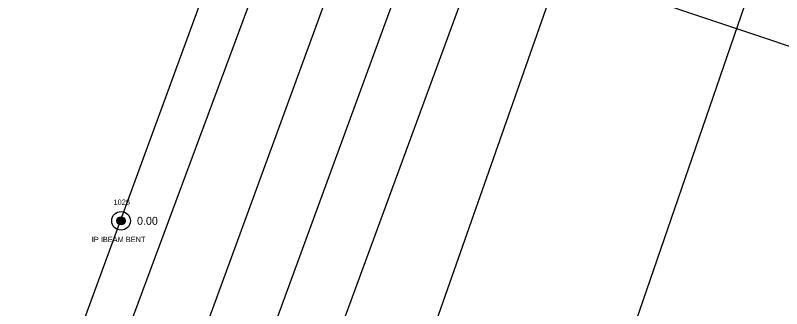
# Model space of a CAD drawing. Extents: x 2139392 to 2143384, y 505395 to 510520.
# Drawn here: x 2140882.2 to 2141025.8, y 508983.1 to 509038.2 of the extents above; entities that cross this region are included whole.
import ezdxf

# ---------------------------------------------------------------- set-up
doc = ezdxf.new("R2010")
doc.units = 0
for name, color, linetype in [('RD_EV_EX_Wetlands', 7, 'Continuous'), ('RD_EX_DV_Prop_txCode', 7, 'Continuous'), ('RD_EX_DV_PropPin', 7, 'Continuous'), ('RD_EX_H2O', 7, 'Continuous'), ('RD_EX_Road', 7, 'Continuous'), ('RD_EX_TX_DV_Prop_ELEV', 7, 'Continuous'), ('RD_EX_VEG', 7, 'Continuous'), ('RD_HC_Cl', 7, 'Continuous'), ('RD_HC_Data', 7, 'Continuous'), ('RD_SMD_Locator', 7, 'Continuous')]:
    doc.layers.add(name, color=color, linetype=linetype)

msp = doc.modelspace()

# ---------------------------------------------------------------- linework, layer by layer
at = {"layer": 'RD_EV_EX_Wetlands'}
for p, q in [((2141031.31, 509324.16), (2140691.53, 508408.63)), ((2141075.3, 509306.14), (2140751.4, 508384.33))]:
    msp.add_line(p, q, dxfattribs=at)
at = {"layer": 'RD_EX_DV_PropPin'}
for p, q in [((2140901.28, 508999.35), (2140901.28, 508999.94)), ((2140901.32, 508999.27), (2140901.32, 509000.01)), ((2140901.35, 508999.22), (2140901.35, 509000.07)), ((2140901.39, 508999.17), (2140901.39, 509000.12)), ((2140901.42, 508999.13), (2140901.42, 509000.16)), ((2140901.46, 508999.09), (2140901.46, 509000.19)), ((2140901.49, 508999.06), (2140901.49, 509000.23)), ((2140901.53, 508999.03), (2140901.53, 509000.25)), ((2140901.56, 508999.01), (2140901.56, 509000.28)), ((2140901.6, 508998.99), (2140901.6, 509000.3)), ((2140901.63, 508998.97), (2140901.63, 509000.32)), ((2140901.67, 508998.95), (2140901.67, 509000.34)), ((2140901.7, 508998.94), (2140901.7, 509000.35)), ((2140901.74, 508998.92), (2140901.74, 509000.36)), ((2140901.77, 508998.91), (2140901.77, 509000.37)), ((2140901.81, 508998.9), (2140901.81, 509000.38)), ((2140901.84, 508998.9), (2140901.84, 509000.39)), ((2140901.88, 508998.89), (2140901.88, 509000.4)), ((2140901.91, 508998.89), (2140901.91, 509000.4)), ((2140901.95, 508998.88), (2140901.95, 509000.4)), ((2140901.98, 508998.88), (2140901.98, 509000.4)), ((2140902.02, 508998.88), (2140902.02, 509000.4)), ((2140902.05, 508998.89), (2140902.05, 509000.4)), ((2140902.09, 508998.89), (2140902.09, 509000.4)), ((2140902.12, 508998.9), (2140902.12, 509000.39)), ((2140902.16, 508998.9), (2140902.16, 509000.38)), ((2140902.19, 508998.91), (2140902.19, 509000.37)), ((2140902.23, 508998.92), (2140902.23, 509000.36)), ((2140902.26, 508998.94), (2140902.26, 509000.35)), ((2140902.3, 508998.95), (2140902.3, 509000.34)), ((2140902.33, 508998.97), (2140902.33, 509000.32)), ((2140902.37, 508998.99), (2140902.37, 509000.3)), ((2140902.4, 508999.01), (2140902.4, 509000.28)), ((2140902.44, 508999.03), (2140902.44, 509000.25)), ((2140902.47, 508999.06), (2140902.47, 509000.23)), ((2140902.51, 508999.09), (2140902.51, 509000.19)), ((2140902.54, 508999.13), (2140902.54, 509000.16)), ((2140902.58, 508999.17), (2140902.58, 509000.12)), ((2140902.61, 508999.22), (2140902.61, 509000.07)), ((2140902.65, 508999.27), (2140902.65, 509000.01)), ((2140902.68, 508999.35), (2140902.68, 508999.94)), ((2140901.25, 508999.45), (2140901.25, 508999.84)), ((2140902.72, 508999.45), (2140902.72, 508999.84))]:
    msp.add_line(p, q, dxfattribs=at)
for radius in [1.75, 0.761]:
    msp.add_circle((2140901.98, 508999.64), radius, dxfattribs=at)
at = {"layer": 'RD_EX_H2O'}
msp.add_lwpolyline([(2140979.84, 509045.53), (2140988.49, 509044.65), (2140996.91, 509042.64), (2141034.47, 509029.98), (2141054.86, 509009.95), (2141076.5, 509008.6), (2141108.93, 509002.88), (2141157.17, 508989.85), (2141167.48, 508991.01), (2141188.81, 509012.46), (2141188.28, 509016.58)], dxfattribs=at)
at = {"layer": 'RD_EX_Road'}
for points in [[(2141086.27, 509371.27), (2141050.42, 509272.83), (2141015.08, 509176.39), (2140981.03, 509083.35), (2140979.15, 509077.9), (2140973.7, 509063.54), (2140966.53, 509043.25), (2140933.44, 508952.99), (2140896.92, 508852.59), (2140862.18, 508757.77), (2140824.9, 508656.32), (2140789.81, 508560.3), (2140766.77, 508496.85), (2140751.9, 508457.03), (2140731.87, 508401.54), (2140727.36, 508390.27)], [(2141052.52, 509348.48), (2141043.48, 509323.88), (2141027.84, 509280.54), (2140992.95, 509184.87), (2140958.53, 509091.45), (2140950.8, 509069.47), (2140944.28, 509052.06), (2140911.45, 508962.1), (2140874.65, 508861.6), (2140839.42, 508765.22), (2140802.38, 508664.56), (2140767.79, 508569.67), (2140744.17, 508504.83), (2140729.49, 508465.07), (2140707.16, 508404.62), (2140705.36, 508398.02)]]:
    msp.add_lwpolyline(points, dxfattribs=at)
at = {"layer": 'RD_EX_VEG'}
for points in [[(2140900.08, 509397.36), (2141021.29, 509326.2), (2140852.61, 508865.26), (2140689.34, 508413.46), (2140624.53, 508226.48), (2140606.41, 508171.78), (2140591.23, 508116.67), (2140558.82, 507962.77), (2140538.78, 507709.07), (2140410.61, 507724.88)], [(2141197.74, 509262.45), (2141108.66, 509301.7), (2140947.3, 508831.92), (2140798.26, 508440.01), (2140718.9, 508193.9), (2140671.92, 508048.02), (2140772.34, 507989.74)]]:
    msp.add_lwpolyline(points, dxfattribs=at)
at = {"layer": 'RD_HC_Cl'}
msp.add_line((2141333.53, 510081.69), (2140670.51, 508268.37), dxfattribs=at)
at = {"layer": 'RD_SMD_Locator'}
msp.add_circle((2140901.98, 508999.64), 0.15, dxfattribs=at)

# ---------------------------------------------------------------- texts
at = {"layer": 'RD_EX_DV_Prop_txCode'}
for s, p in [('1026', (2140900.58, 509002.64)), ('IP IBEAM BENT', (2140896.51, 508995.64))]:
    msp.add_text(s, height=1, dxfattribs=at).set_placement(p)
at = {"layer": 'RD_EX_TX_DV_Prop_ELEV'}
msp.add_text('0.00', height=1.5, dxfattribs=at).set_placement((2140904.98, 508998.89))
at = {"layer": 'RD_HC_Data'}
msp.add_text('S 69%%d 53\' 54" E', height=6, rotation=339.8984, dxfattribs=at).set_placement((2140993.38, 509052.62))

doc.saveas('drawing.dxf')
